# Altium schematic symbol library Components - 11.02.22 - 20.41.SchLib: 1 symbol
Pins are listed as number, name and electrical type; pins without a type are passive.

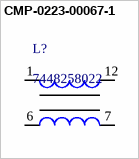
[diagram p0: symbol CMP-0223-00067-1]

## CMP-0223-00067-1
designator L?, comment 7448258022
THT Common Mode Power Line Choke WE-CMB, L = 2.20 mH; Inductance: 2.20 mH
footprint WE-CMB-XL (THT Inductor, 4-Leads, Body 30.0 x 21.0 mm)
pins: 1, 6, 7, 12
